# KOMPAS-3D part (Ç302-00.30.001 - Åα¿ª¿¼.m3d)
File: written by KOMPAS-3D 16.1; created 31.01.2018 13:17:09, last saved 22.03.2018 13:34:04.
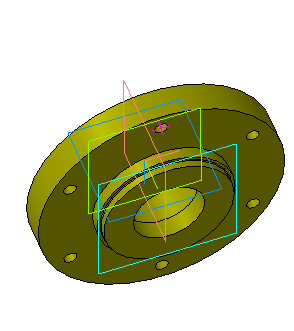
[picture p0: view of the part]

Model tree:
1. Эскиз:1
2. Операция вращения:1
     Угол 1 = 360
3. Условное изображение резьбы:1  (labels: M80x3)
     Длина резьбы = 20; Шаг резьбы = 3; Номинальный диаметр резьбы = 80
4. Подгонка:1
5. Эскиз:3
6. Операция выдавливания:1
     Расстояние 1 = 10; Расстояние 2 = 14
7. Эскиз:5
8. Отверстие:1
     Глубина выреза = 20; Диаметр отверстия = 6; Угол конуса торца = 118; Координата Y = 47
9. Массив по концентрической сетке:1  (with: Отверстие:1, Эскиз:5)  (6 pattern instances)
     Геометрический массив = 5; Шаг 2 = 360
10. Эскиз:6
11. Операция выдавливания:2
     Расстояние 1 = 9; Расстояние 2 = 14
12. Смещенная плоскость:1
     Расстояние = 2
13. Эскиз:9
14. Вырезать элемент выдавливания:3
     Расстояние 1 = 3.6
15. Скругление:1
     Радиус = 0.4
16. Эскиз:10
17. Вырезать элемент выдавливания:4
     Расстояние 1 = 20.5
18. Фаска:5  (labels: Полипропилен  ГОСТ 26996-86)
     Угол = 45; Длина 1 = 1; Длина 2 = 1

Referenced files in C:\Program Files\ASCON\KOMPAS-3D V16\Sys\Thread\: cil0_8724-2002 fine.xml
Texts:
  Линейный размер с обрывом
